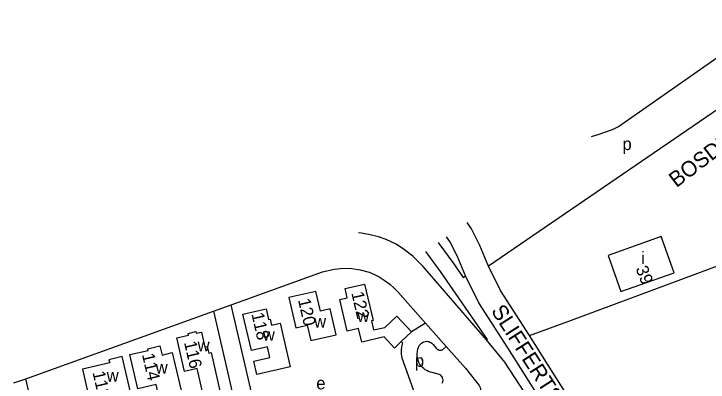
# Model space of a CAD drawing. Extents: x 155696 to 157795, y 382328 to 384028.
# Drawn here: x 157061.7 to 157284.9, y 383706.4 to 383824.6 of the extents above; entities that cross this region are included whole.
import ezdxf

# ---------------------------------------------------------------- set-up
doc = ezdxf.new("R2010")
doc.units = 0
for name, color, linetype in [('BLT_Basislijn', 7, 'Continuous'), ('BLT_Bebouwing', 7, 'Continuous'), ('BLT_Centroide', 7, 'Continuous'), ('BLT_Huisnummer', 7, 'Continuous'), ('BLT_Straatnaam', 7, 'Continuous')]:
    doc.layers.add(name, color=color, linetype=linetype)

msp = doc.modelspace()

# ---------------------------------------------------------------- linework, layer by layer
at = {"layer": 'BLT_Basislijn'}
for p, q in [((157256.07, 383788.51), (157307.92, 383824.64)), ((157317.19, 383813.98), (157214.3, 383743.57)), ((157125.93, 383729.11), (157131.62, 383731.15)), ((157194.05, 383725.3), (157189.56, 383722.51)), ((157061.7, 383706.08), (157065.49, 383707.44))]:
    msp.add_line(p, q, dxfattribs=at)
for points in [[(157247.39, 383785.23), (157249.62, 383785.87), (157254.23, 383787.51), (157256.07, 383788.51)], [(157214.3, 383743.57), (157214.17, 383743.82), (157211.48, 383750.28), (157208.8, 383755.62), (157207.44, 383757.6)], [(157227.49, 383721.31), (157241.04, 383726.3), (157325.16, 383757.5)], [(157213.71, 383719.96), (157193.29, 383743.45), (157189.98, 383746.78), (157187.34, 383748.9), (157184.66, 383750.63), (157181.42, 383752.19), (157178.98, 383752.98), (157176.29, 383753.68), (157173.52, 383754.18), (157172.48, 383754.28)], [(157198.18, 383751.19), (157198.39, 383750.92), (157202.86, 383744.79), (157206.18, 383740), (157206.89, 383740.5)], [(157206.89, 383740.5), (157204.2, 383746.94), (157201.9, 383751.54), (157200.86, 383753.04)], [(157194.06, 383748.34), (157194.39, 383747.91), (157198.79, 383741.89), (157213.91, 383720.09), (157213.71, 383719.96)], [(157131.62, 383731.15), (157160.91, 383741.76), (157164.71, 383742.66), (157167.8, 383742.93), (157170.41, 383742.85), (157173.05, 383742.47), (157175.93, 383741.69), (157177.63, 383740.98), (157179.12, 383740.18), (157180.82, 383739.13), (157182.56, 383737.87), (157183.96, 383736.59), (157185.15, 383735.34), (157194.05, 383725.3)], [(157227.49, 383721.31), (157218.19, 383735.74), (157214.3, 383743.57)], [(157233.26, 383697.28), (157220.49, 383717.4), (157211.23, 383731.78), (157206.89, 383740.5)], [(157187.92, 383696.99), (157141.96, 383686.41), (157131.62, 383731.15)], [(157065.49, 383707.44), (157125.93, 383729.11)], [(157125.93, 383729.11), (157136.11, 383685.06), (157073.98, 383670.71), (157065.49, 383707.44)], [(157194.05, 383725.3), (157200.69, 383717.82)], [(157226.05, 383702.9), (157219.52, 383712.77), (157213.71, 383719.96)], [(157233.51, 383711.82), (157227.49, 383721.31)], [(157186.26, 383719.39), (157186.7, 383718.93), (157186.34, 383717.73), (157186.19, 383716.57), (157186.23, 383715.39), (157186.47, 383714.16), (157191.17, 383700.99), (157190.18, 383700.64)], [(157199.43, 383706.07), (157199.6, 383706.47), (157199.69, 383706.94), (157199.66, 383707.39), (157199.52, 383707.82), (157199.3, 383708.2), (157198.99, 383708.54), (157198.6, 383708.8), (157198.13, 383708.96), (157196.22, 383709.4), (157195.62, 383709.56), (157195.04, 383709.78), (157194.48, 383710.05), (157194, 383710.34), (157193.5, 383710.7), (157193.08, 383711.06), (157192.66, 383711.49), (157192.25, 383711.99), (157191.93, 383712.62), (157191.67, 383713.34), (157191.49, 383714.09), (157191.4, 383714.83), (157191.39, 383715.49), (157191.47, 383716.31), (157191.62, 383716.99), (157191.88, 383717.75), (157192.07, 383718.15), (157192.32, 383718.49), (157192.72, 383718.88), (157193.1, 383719.13), (157193.5, 383719.31), (157194.02, 383719.43), (157194.38, 383719.46), (157194.76, 383719.44), (157195.11, 383719.36), (157195.46, 383719.24), (157195.78, 383719.08), (157196.07, 383718.89), (157196.31, 383718.68), (157196.54, 383718.42), (157197.53, 383717.29), (157197.82, 383716.99), (157198.13, 383716.8), (157198.47, 383716.67), (157198.83, 383716.62), (157199.24, 383716.67), (157199.6, 383716.79), (157200.69, 383717.82)], [(157200.69, 383717.82), (157206.91, 383710.81), (157211.31, 383705.3), (157211.69, 383704.41), (157211.59, 383703.4), (157211.14, 383702.68)], [(157242.84, 383697.16), (157241.7, 383698.91), (157233.51, 383711.82)]]:
    msp.add_lwpolyline(points, dxfattribs=at)
at = {"layer": 'BLT_Bebouwing'}
for points in [[(157252.78, 383747.06), (157256.92, 383735.43), (157273.98, 383741.47), (157269.85, 383753.11)], [(157150.07, 383733.52), (157152.38, 383723.77), (157156, 383724.61), (157157.14, 383719.69), (157165.34, 383721.59), (157163.43, 383729.85), (157160.31, 383729.14), (157158.84, 383735.52)], [(157135.37, 383728.22), (157142.77, 383729.92), (157143.57, 383726.42), (157144.12, 383726.54), (157144.55, 383724.66), (157147.3, 383725.29), (157150.5, 383711.28), (157139.83, 383708.82), (157138.86, 383713.04), (157144.02, 383714.23), (157143.22, 383717.72), (157138.06, 383716.53)], [(157114.1, 383720.62), (157117.85, 383721.48), (157117.73, 383722.02), (157120.18, 383722.58), (157120.31, 383722.05), (157122.02, 383722.44), (157123.14, 383717.62), (157123.89, 383717.8), (157124.38, 383715.65), (157125.13, 383715.82), (157127.97, 383703.53), (157122.6, 383702.29), (157120.65, 383710.75), (157116.6, 383709.81)], [(157098.99, 383715.2), (157104.86, 383716.55), (157104.74, 383717.08), (157108.65, 383717.98), (157109.33, 383715.06), (157112.64, 383715.83), (157115.87, 383701.85), (157108.64, 383700.18), (157107.4, 383705.54), (157101.54, 383704.19)]]:
    msp.add_lwpolyline(points, close=True, dxfattribs=at)
for points in [[(157168.22, 383736.38), (157174.49, 383737.83), (157177.18, 383726.15), (157176.66, 383726.03), (157177.33, 383723.12), (157180.94, 383723.94), (157184.82, 383727.54), (157189.56, 383722.51)], [(157186.26, 383719.39), (157184.05, 383717.31), (157180.77, 383720.86), (157173.57, 383719.19), (157172.55, 383723.6), (157168.89, 383722.76), (157166.54, 383732.93), (157168.9, 383733.47), (157168.22, 383736.38)], [(157189.56, 383722.51), (157186.26, 383719.39)], [(157096.57, 383714.54), (157092.27, 383713.55), (157092.51, 383712.52), (157083.72, 383710.49), (157086.45, 383698.66), (157094.07, 383700.42), (157094.02, 383700.65), (157095.19, 383700.92), (157095.66, 383698.89), (157099.96, 383699.89), (157096.57, 383714.54)]]:
    msp.add_lwpolyline(points, dxfattribs=at)

# ---------------------------------------------------------------- texts
at = {"layer": 'BLT_Centroide'}
for s, p in [('p', (157257.39, 383780.89)), ('i', (157263.38, 383744.28)), ('w', (157172.11, 383725.67)), ('w', (157158.25, 383723.87)), ('w', (157141.75, 383719.63)), ('w', (157120.77, 383716.25)), ('p', (157190.64, 383711.26)), ('w', (157107.3, 383709.09)), ('w', (157091.54, 383706.5)), ('e', (157158.94, 383704.03))]:
    msp.add_text(s, height=4, dxfattribs=at).set_placement(p)
at = {"layer": 'BLT_Huisnummer'}
for s, rotation, p in [('39', 291.6119, (157261.55, 383742.83)), ('122', 283.0066, (157170.18, 383735.01)), ('120', 283.0066, (157153.03, 383732.79)), ('118', 283.0066, (157138.06, 383728.26)), ('116', 283.0079, (157116.37, 383719.11)), ('114', 283.0079, (157102.87, 383715.21)), ('112', 283.0079, (157086.96, 383709.49))]:
    msp.add_text(s, height=4, rotation=rotation, dxfattribs=at).set_placement(p)
at = {"layer": 'BLT_Straatnaam'}
for s, rotation, p in [('BOSDUIN', 37.4543, (157274.75, 383768.65)), ('SLIFFERTSESTRAAT', 302.6652, (157214.99, 383729.25))]:
    msp.add_text(s, height=5, rotation=rotation, dxfattribs=at).set_placement(p)

doc.saveas('drawing.dxf')
